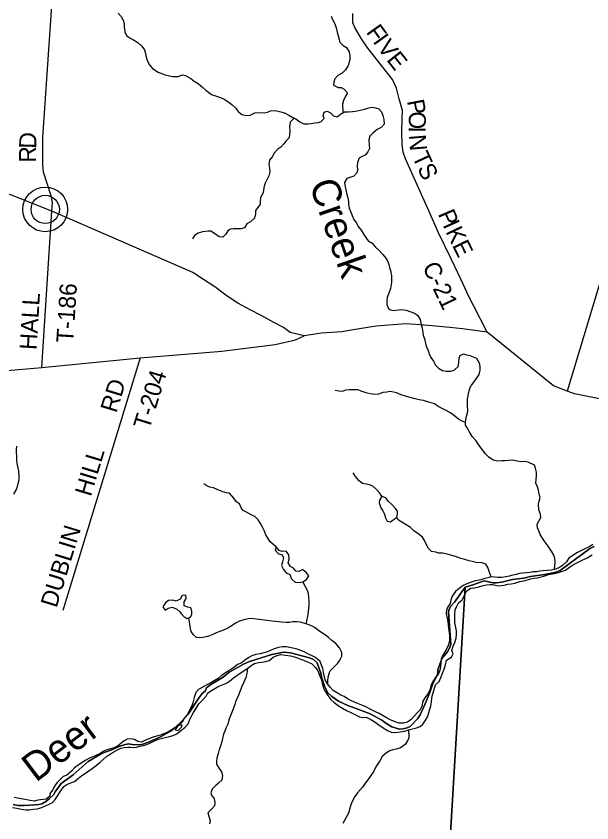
# Model space of a CAD drawing. Extents: x 1643459 to 2064572, y 425441 to 780708.
# Drawn here: x 1774988 to 1785105, y 584838 to 599024 of the extents above; entities that cross this region are included whole.
import ezdxf

# ---------------------------------------------------------------- set-up
doc = ezdxf.new("R2010")
doc.units = 0
for name, color, linetype in [('GE_P_Alignment_100_Curve_Data', 7, 'Continuous'), ('GM_X_City_Street', 7, 'Continuous'), ('GM_X_Interchange_Ramps', 7, 'Continuous'), ('GM_X_Major_River', 7, 'Continuous'), ('GM_X_Major_River_Text', 7, 'Continuous'), ('GM_X_Minor_Lake', 7, 'Continuous'), ('GM_X_Rail_Line', 7, 'Continuous'), ('GM_X_Section_Text', 7, 'Continuous'), ('GM_X_State_Shield', 7, 'Continuous'), ('GM_X_Township_Subdivision_Text', 7, 'Continuous'), ('GM_X_Unincorporated_Text', 7, 'Continuous'), ('GM_X_US_Route', 7, 'Continuous')]:
    doc.layers.add(name, color=color, linetype=linetype)

msp = doc.modelspace()

# ---------------------------------------------------------------- linework, layer by layer
at = {"layer": 'GE_P_Alignment_100_Curve_Data'}
for radius in [393, 249]:
    msp.add_circle((1775499, 595625), radius, dxfattribs=at)
at = {"layer": 'GM_X_City_Street'}
for points in [[(1785145, 589695), (1785063, 589654), (1784546, 589274), (1784474, 589244), (1784280, 589203), (1784028, 589172), (1783911, 589141), (1783711, 589116), (1783521, 589072), (1783425, 589061), (1783363, 589061), (1783215, 589096), (1783016, 589021), (1782878, 588982), (1782690, 588716), (1782624, 588650), (1782596, 588598), (1782584, 588542), (1782625, 587974), (1782600, 587898), (1782566, 587844), (1782481, 587740), (1782459, 587690), (1782396, 587526), (1782400, 587454), (1782358, 587382), (1782305, 587268), (1782264, 587148), (1782175, 586930), (1782088, 586740), (1782042, 586666), (1781913, 586530), (1781861, 586506), (1781789, 586490), (1781723, 586483), (1781591, 586526), (1781483, 586588), (1781413, 586645), (1781210, 586756), (1780900, 586874), (1780826, 586895), (1780651, 586980), (1780533, 587057), (1780465, 587127), (1780408, 587240), (1780362, 587381), (1780351, 587455), (1780276, 587652), (1780212, 587710), (1780142, 587741), (1779812, 587829), (1779684, 587838), (1779484, 587801), (1779089, 587676), (1778973, 587621), (1778728, 587480), (1778625, 587398), (1778391, 587261), (1778334, 587211), (1778310, 587155), (1778256, 587111), (1778205, 587043), (1778008, 586748), (1777895, 586620), (1777774, 586506), (1777710, 586458), (1777525, 586351), (1777283, 586244), (1777197, 586217), (1777056, 586207), (1776960, 586226), (1776886, 586210), (1776808, 586187), (1776668, 586121), (1776537, 586074), (1776421, 586016), (1776252, 585915), (1775989, 585682), (1775776, 585530), (1775671, 585384), (1775645, 585332), (1775573, 585265), (1775508, 585213), (1775442, 585175), (1775388, 585159), (1775318, 585152), (1775134, 585141), (1775022, 585143), (1774936, 585160)], [(1785638, 551176), (1783571, 551280), (1780637, 551427), (1780907, 555957), (1781210, 561021), (1781241, 561540), (1781479, 565536), (1782039, 574916), (1782573, 583864), (1782878, 588982), (1783016, 589021), (1783215, 589096), (1783363, 589061), (1783425, 589061), (1783521, 589072), (1783711, 589116), (1783911, 589141), (1784028, 589172), (1784280, 589203), (1784474, 589244), (1784546, 589274), (1785063, 589654), (1785145, 589695)], [(1774936, 585160), (1775022, 585143), (1775134, 585141), (1775318, 585152), (1775388, 585159), (1775442, 585175), (1775508, 585213), (1775573, 585265), (1775645, 585332), (1775671, 585384), (1775776, 585530), (1775989, 585682), (1776252, 585915), (1776421, 586016), (1776537, 586074), (1776668, 586121), (1776808, 586187), (1776886, 586210), (1776960, 586226), (1777056, 586207), (1777197, 586217), (1777283, 586244), (1777525, 586351), (1777710, 586458), (1777774, 586506), (1777895, 586620), (1778008, 586748), (1778205, 587043), (1778256, 587111), (1778310, 587155), (1778334, 587211), (1778391, 587261), (1778625, 587398), (1778728, 587480), (1778973, 587621), (1779089, 587676), (1779484, 587801), (1779684, 587838), (1779812, 587829), (1780142, 587741), (1780212, 587710), (1780276, 587652), (1780351, 587455), (1780362, 587381), (1780408, 587240), (1780465, 587127), (1780533, 587057), (1780651, 586980), (1780826, 586895), (1780900, 586874), (1781210, 586756), (1781413, 586645), (1781483, 586588), (1781591, 586526), (1781723, 586483), (1781789, 586490), (1781861, 586506), (1781913, 586530), (1782042, 586666), (1782088, 586740), (1782175, 586930), (1782264, 587148), (1782305, 587268), (1782358, 587382), (1782400, 587454), (1782396, 587526), (1782459, 587690), (1782481, 587740), (1782566, 587844), (1782600, 587898), (1782625, 587974), (1782584, 588542), (1782596, 588598), (1782624, 588650), (1782690, 588716), (1782878, 588982), (1782573, 583864)]]:
    msp.add_lwpolyline(points, dxfattribs=at)
at = {"layer": 'GM_X_Major_River_Text'}
for points in [[(1785328, 606791), (1786619, 602390), (1786660, 602213), (1786853, 601568), (1786925, 601173), (1786882, 600934), (1786380, 597820), (1786372, 597734), (1786255, 597600), (1785662, 596965), (1785638, 596798), (1785873, 595554), (1785859, 595459), (1785408, 594758), (1785283, 594487), (1785225, 594273), (1784673, 592431)], [(1775613, 595594), (1775628, 595745), (1775605, 595867), (1775470, 596279), (1775455, 596409), (1775456, 596891), (1775858, 602814), (1775878, 602941), (1775893, 603105), (1775919, 603416), (1775936, 603556), (1775980, 603638), (1776241, 603970), (1776327, 604068), (1776452, 604256), (1776531, 604386), (1776729, 604627), (1776882, 604731), (1777131, 604864), (1777265, 604900), (1779128, 605436)], [(1775439, 592847), (1775613, 595594)], [(1777170, 593015), (1775811, 588571)]]:
    msp.add_lwpolyline(points, dxfattribs=at)
at = {"layer": 'GM_X_Minor_Lake'}
for points in [[(1783266, 593466), (1783028, 593933), (1782946, 594092), (1782804, 594401), (1782627, 594767), (1782411, 595212), (1782241, 595598), (1781831, 596516), (1781792, 596631), (1781772, 596765), (1781768, 596986), (1781773, 597227), (1781776, 597363), (1781721, 597572), (1781670, 597759), (1781602, 597908), (1781344, 598240), (1781166, 598461), (1781057, 598626), (1780944, 598813), (1780902, 598906), (1780905, 599068)], [(1783266, 593466), (1782829, 593523), (1782607, 593550), (1782301, 593577), (1782006, 593599), (1781838, 593612), (1781317, 593572), (1780912, 593508), (1780713, 593475), (1780354, 593449), (1780048, 593400), (1779803, 593461), (1779688, 593546), (1779514, 593637), (1779304, 593753), (1779102, 593858), (1778885, 593979), (1778699, 594101), (1778479, 594264), (1778282, 594394), (1778090, 594513), (1775613, 595594), (1772804, 596711)], [(1792934, 588598), (1792450, 588716), (1791683, 588942), (1788162, 590231), (1787955, 590362), (1786367, 591862), (1785471, 592247), (1784800, 592384), (1784673, 592431), (1784433, 592524), (1783266, 593466)], [(1773680, 592693), (1775439, 592847), (1777170, 593015), (1778600, 593134), (1779540, 593250), (1779895, 593329), (1780048, 593400)]]:
    msp.add_lwpolyline(points, dxfattribs=at)
at = {"layer": 'GM_X_Rail_Line'}
msp.add_line((1775499, 595625), (1775499, 595625), dxfattribs=at)
at = {"layer": 'GM_X_Township_Subdivision_Text'}
msp.add_line((1780086, 589242), (1780052, 589271), dxfattribs=at)
for points in [[(1781602, 590422), (1781528, 590492), (1781488, 590549), (1781416, 590581), (1781374, 590513), (1781366, 590463), (1781395, 590377), (1781429, 590326), (1781461, 590268), (1781481, 590200), (1781510, 590142), (1781566, 590131), (1781677, 590215)], [(1781677, 590215), (1781689, 590265), (1781691, 590317), (1781650, 590373), (1781602, 590422)], [(1779557, 589691), (1779539, 589631), (1779600, 589570), (1779660, 589550), (1779688, 589498), (1779666, 589429), (1779651, 589361), (1779685, 589291), (1779735, 589235), (1779797, 589204), (1779828, 589130), (1779890, 589073), (1779966, 589065), (1780026, 589076), (1780088, 589120), (1780129, 589180), (1780086, 589242)], [(1780052, 589271), (1780025, 589291), (1779955, 589259), (1779905, 589264), (1779861, 589318), (1779809, 589346), (1779770, 589409), (1779784, 589475), (1779782, 589553), (1779735, 589614), (1779663, 589610), (1779611, 589630), (1779557, 589691)], [(1777862, 588546), (1777890, 588518), (1777932, 588468), (1777990, 588432), (1778050, 588455), (1778074, 588507), (1778076, 588562), (1778059, 588620), (1778007, 588630), (1777941, 588655), (1777941, 588723), (1777975, 588783), (1777968, 588839), (1777906, 588835), (1777871, 588773), (1777801, 588734), (1777739, 588754), (1777665, 588746), (1777611, 588709), (1777568, 588639), (1777606, 588576)], [(1777606, 588576), (1777662, 588614), (1777728, 588628), (1777812, 588595), (1777862, 588546)]]:
    msp.add_lwpolyline(points, dxfattribs=at)
at = {"layer": 'GM_X_Unincorporated_Text'}
for points in [[(1785125, 589731), (1785062, 589689), (1784992, 589663), (1784926, 589630), (1784852, 589592), (1784789, 589550), (1784697, 589486), (1784657, 589427), (1784592, 589363), (1784536, 589331), (1784472, 589299), (1784394, 589282), (1784320, 589276), (1784248, 589272), (1784192, 589261), (1784130, 589251), (1784074, 589251), (1784013, 589241), (1783959, 589234), (1783889, 589226), (1783833, 589220), (1783777, 589207), (1783719, 589195), (1783653, 589177), (1783595, 589164), (1783515, 589152), (1783453, 589154), (1783403, 589157), (1783337, 589163), (1783277, 589145), (1783222, 589135), (1783152, 589110), (1783038, 589088), (1782966, 589065), (1782898, 589033), (1782846, 589011), (1782771, 588959), (1782709, 588906), (1782649, 588826), (1782626, 588754), (1782614, 588693), (1782572, 588634), (1782549, 588577), (1782545, 588517), (1782561, 588435), (1782572, 588381), (1782582, 588315), (1782586, 588262), (1782599, 588180), (1782603, 588130), (1782601, 588064), (1782598, 588008), (1782582, 587958), (1782556, 587904), (1782522, 587848), (1782479, 587776), (1782459, 587718), (1782453, 587653), (1782448, 587581), (1782432, 587521), (1782408, 587457), (1782353, 587387), (1782303, 587311), (1782276, 587245), (1782260, 587171), (1782222, 587109), (1782169, 587037), (1782127, 586965)], [(1782236, 586754), (1782254, 586818), (1782273, 586890), (1782285, 586962), (1782293, 587030), (1782304, 587089), (1782326, 587165), (1782359, 587263), (1782421, 587325), (1782457, 587407), (1782482, 587469), (1782512, 587539), (1782532, 587615), (1782553, 587697), (1782639, 587753), (1782666, 587809), (1782642, 587871), (1782666, 587943), (1782695, 588011), (1782723, 588085), (1782725, 588151), (1782726, 588214), (1782710, 588304), (1782700, 588358), (1782695, 588428), (1782697, 588490), (1782705, 588581), (1782730, 588647), (1782764, 588707), (1782824, 588761), (1782865, 588843), (1782905, 588911), (1782971, 588962), (1783042, 588972), (1783120, 588990), (1783196, 589011), (1783252, 589023), (1783316, 589029), (1783366, 589032), (1783458, 589008), (1783510, 589010), (1783562, 589019), (1783628, 589035), (1783690, 589043), (1783752, 589052), (1783837, 589080), (1783907, 589096), (1784035, 589127), (1784085, 589139), (1784143, 589149), (1784263, 589178), (1784341, 589206), (1784446, 589225), (1784504, 589233), (1784574, 589256), (1784642, 589282), (1784710, 589334), (1784763, 589368), (1784843, 589411), (1784897, 589441), (1785023, 589497), (1785110, 589552)], [(1782127, 586965), (1782123, 586903), (1782088, 586827), (1782038, 586771), (1781986, 586717), (1781927, 586653), (1781867, 586610), (1781797, 586588), (1781721, 586590), (1781667, 586607), (1781561, 586651), (1781507, 586676), (1781437, 586722), (1781370, 586763), (1781304, 586793), (1781220, 586834), (1781132, 586880), (1781060, 586909), (1780974, 586941), (1780882, 586982), (1780810, 587018), (1780751, 587059), (1780693, 587083), (1780615, 587128), (1780559, 587168), (1780509, 587223), (1780458, 587285), (1780418, 587350), (1780404, 587406), (1780392, 587484), (1780377, 587550), (1780353, 587611), (1780333, 587673), (1780246, 587744), (1780190, 587774), (1780124, 587806), (1780036, 587849), (1779964, 587883), (1779906, 587900), (1779818, 587918), (1779736, 587933), (1779664, 587933), (1779600, 587922), (1779520, 587898), (1779468, 587874), (1779390, 587842), (1779340, 587825), (1779277, 587813), (1779199, 587799), (1779127, 587772), (1779077, 587746), (1778999, 587690), (1778940, 587648), (1778880, 587623), (1778806, 587565), (1778695, 587495), (1778597, 587432), (1778539, 587378), (1778467, 587336), (1778412, 587300), (1778352, 587272), (1778288, 587235), (1778190, 587183), (1778143, 587129), (1778119, 587045), (1778092, 586951), (1778076, 586895), (1778040, 586833), (1778001, 586745), (1777949, 586685), (1777903, 586609), (1777846, 586555), (1777780, 586515), (1777710, 586470), (1777656, 586432), (1777595, 586408), (1777523, 586380), (1777453, 586363), (1777395, 586343), (1777317, 586317), (1777259, 586292), (1777188, 586254), (1777124, 586268), (1777070, 586301), (1776996, 586313), (1776936, 586307), (1776886, 586280), (1776766, 586184), (1776706, 586158), (1776631, 586131), (1776581, 586119), (1776517, 586095), (1776463, 586059), (1776387, 586020), (1776330, 585998), (1776274, 585974), (1776198, 585932), (1776142, 585896), (1776078, 585855), (1776015, 585803), (1775963, 585747)], [(1776086, 585624), (1776145, 585670), (1776207, 585714), (1776267, 585753), (1776325, 585795), (1776396, 585849), (1776458, 585897), (1776516, 585953), (1776575, 586002), (1776629, 586038), (1776707, 586088), (1776769, 586124), (1776826, 586152), (1776884, 586165), (1776948, 586169), (1777000, 586169), (1777052, 586164), (1777104, 586170), (1777162, 586184), (1777224, 586198), (1777284, 586217), (1777336, 586237), (1777419, 586281), (1777491, 586308), (1777559, 586326), (1777609, 586336), (1777685, 586355), (1777749, 586375), (1777813, 586405), (1777878, 586457), (1777952, 586512), (1778010, 586582), (1778037, 586642), (1778075, 586724), (1778106, 586776), (1778146, 586842), (1778200, 586928), (1778261, 586998), (1778327, 587066), (1778355, 587122), (1778418, 587168), (1778508, 587217), (1778566, 587249), (1778628, 587273), (1778686, 587293), (1778739, 587329), (1778807, 587390), (1778867, 587432), (1779066, 587563), (1779120, 587605), (1779179, 587641), (1779249, 587655), (1779307, 587662), (1779377, 587676), (1779433, 587690), (1779503, 587754), (1779577, 587783), (1779636, 587797), (1779722, 587788), (1779810, 587772), (1779896, 587753), (1779975, 587725), (1780067, 587686), (1780121, 587664), (1780179, 587638), (1780251, 587567), (1780289, 587513), (1780320, 587436), (1780348, 587364), (1780373, 587270), (1780391, 587213), (1780413, 587157), (1780463, 587076), (1780516, 587008), (1780576, 586954), (1780644, 586903), (1780724, 586854), (1780793, 586816), (1780845, 586792), (1780905, 586759), (1780963, 586729), (1781023, 586700), (1781079, 586690), (1781141, 586694), (1781221, 586657), (1781281, 586619), (1781359, 586560), (1781440, 586506), (1781512, 586461), (1781576, 586431), (1781660, 586424), (1781738, 586436), (1781820, 586451), (1781882, 586471), (1781951, 586489), (1782003, 586501), (1782087, 586534), (1782137, 586576), (1782175, 586634), (1782216, 586700), (1782236, 586754)], [(1777903, 586560), (1777831, 586542), (1777782, 586476), (1777834, 586462), (1777867, 586494)], [(1777867, 586494), (1777896, 586523), (1777903, 586560)], [(1774925, 585107), (1775001, 585096), (1775083, 585078), (1775161, 585065), (1775217, 585067), (1775285, 585081), (1775355, 585086), (1775437, 585106), (1775514, 585142), (1775568, 585164), (1775626, 585197), (1775672, 585251), (1775711, 585303), (1775747, 585363), (1775783, 585419), (1775824, 585475), (1775878, 585513), (1775932, 585533), (1776012, 585566), (1776086, 585624)], [(1775963, 585747), (1775877, 585679), (1775812, 585654), (1775762, 585602), (1775708, 585548), (1775663, 585484), (1775631, 585420), (1775577, 585356), (1775577, 585306), (1775514, 585252), (1775418, 585241), (1775368, 585239), (1775308, 585221), (1775232, 585230), (1775178, 585240), (1775112, 585252), (1775016, 585273), (1774952, 585281)]]:
    msp.add_lwpolyline(points, dxfattribs=at)
at = {"layer": 'GM_X_US_Route'}
for points in [[(1776781, 599075), (1776833, 599015), (1776869, 598954), (1776884, 598896), (1776886, 598834), (1776899, 598747), (1776927, 598685), (1776991, 598639), (1777051, 598606), (1777129, 598560), (1777196, 598495), (1777242, 598430), (1777259, 598366), (1777275, 598304), (1777289, 598249), (1777324, 598175), (1777386, 598106), (1777482, 598038), (1777606, 597989), (1777658, 597978), (1777734, 597962), (1777834, 597965), (1777912, 597991), (1777963, 597983), (1778056, 597926), (1778118, 597882), (1778184, 597841), (1778266, 597768), (1778322, 597722), (1778419, 597647), (1778491, 597623), (1778581, 597594), (1778641, 597562), (1778705, 597525), (1778781, 597468), (1778849, 597406), (1778892, 597345), (1778952, 597293), (1779032, 597274), (1779101, 597284), (1779183, 597324), (1779279, 597331), (1779353, 597325), (1779404, 597335), (1779460, 597356), (1779544, 597362), (1779660, 597337), (1779716, 597315), (1779778, 597284), (1779848, 597240), (1779900, 597217), (1779972, 597167), (1780044, 597130), (1780120, 597128), (1780172, 597136), (1780236, 597147), (1780299, 597153), (1780351, 597171), (1780399, 597225), (1780382, 597279), (1780402, 597337), (1780454, 597355), (1780510, 597326), (1780564, 597270), (1780632, 597256), (1780685, 597299), (1780761, 597343), (1780827, 597339), (1780896, 597348), (1780948, 597354), (1781012, 597366), (1781062, 597374), (1781118, 597387), (1781183, 597411), (1781239, 597421), (1781309, 597414), (1781361, 597394), (1781409, 597344), (1781432, 597279), (1781450, 597205), (1781453, 597127), (1781403, 597063), (1781334, 597029), (1781254, 596969), (1781203, 596913), (1781187, 596847), (1781194, 596757), (1781196, 596698), (1781167, 596640), (1781121, 596582), (1781068, 596555), (1781018, 596529)], [(1780524, 599025), (1780546, 598966), (1780590, 598890), (1780613, 598820), (1780627, 598745), (1780644, 598679), (1780666, 598614), (1780674, 598564), (1780735, 598508), (1780793, 598471), (1780841, 598399), (1780850, 598322), (1780850, 598270), (1780841, 598212), (1780823, 598154), (1780778, 598080), (1780718, 598024), (1780643, 597980), (1780591, 597924), (1780568, 597860), (1780566, 597808), (1780648, 597767), (1780700, 597767), (1780754, 597741), (1780808, 597676), (1780773, 597616), (1780738, 597540)], [(1780738, 597540), (1780724, 597474), (1780729, 597332)], [(1779872, 597230), (1779803, 597160), (1779793, 597077), (1779800, 597019), (1779794, 596933), (1779779, 596881), (1779725, 596827), (1779692, 596777), (1779642, 596719), (1779584, 596683), (1779519, 596611), (1779494, 596557), (1779440, 596493), (1779427, 596423), (1779441, 596353), (1779448, 596288), (1779430, 596214), (1779401, 596156), (1779363, 596084), (1779344, 596034), (1779336, 595968), (1779327, 595914), (1779283, 595832), (1779278, 595767), (1779276, 595717), (1779235, 595659), (1779197, 595605), (1779196, 595545), (1779176, 595469), (1779107, 595407), (1779043, 595371), (1779000, 595303), (1778938, 595283), (1778884, 595286), (1778810, 595284), (1778757, 595280), (1778707, 595250), (1778673, 595188), (1778622, 595136), (1778554, 595145), (1778492, 595189), (1778412, 595240), (1778360, 595244), (1778262, 595229), (1778187, 595205), (1778123, 595165), (1778085, 595109)], [(1781018, 596529), (1780989, 596451), (1780983, 596386), (1780985, 596324), (1780974, 596268), (1780920, 596210), (1780867, 596190), (1780797, 596171), (1780758, 596099), (1780762, 596048), (1780776, 595996), (1780791, 595912), (1780817, 595831), (1780826, 595765), (1780830, 595709), (1780839, 595650), (1780867, 595578), (1780891, 595516), (1780924, 595449), (1780968, 595385), (1780999, 595324), (1781049, 595262), (1781105, 595175), (1781176, 595074), (1781244, 595030), (1781302, 594963), (1781363, 594907), (1781431, 594834), (1781485, 594768), (1781518, 594709), (1781536, 594659), (1781550, 594601), (1781569, 594550), (1781583, 594458), (1781584, 594400), (1781582, 594341), (1781569, 594233), (1781537, 594155), (1781508, 594075), (1781502, 594025), (1781501, 593952), (1781537, 593872), (1781605, 593845), (1781707, 593857), (1781765, 593863), (1781843, 593854), (1781987, 593799), (1782041, 593763), (1782087, 593688), (1782100, 593626), (1782124, 593535), (1782141, 593415), (1782166, 593350), (1782196, 593222), (1782231, 593147), (1782247, 593083), (1782276, 593021), (1782322, 592956), (1782358, 592888), (1782413, 592833), (1782479, 592795), (1782549, 592780), (1782620, 592780), (1782688, 592796), (1782754, 592861), (1782767, 592930), (1782774, 593008), (1782790, 593058), (1782850, 593084), (1782902, 593069), (1782958, 593057), (1783018, 593033), (1783078, 593012), (1783126, 592926), (1783137, 592861), (1783139, 592797), (1783116, 592723), (1783086, 592669), (1782981, 592524)], [(1782883, 591877), (1782828, 591903), (1782762, 591936), (1782668, 592015), (1782611, 592053), (1782535, 592096), (1782477, 592124), (1782405, 592162), (1782337, 592207), (1782263, 592229), (1782201, 592248), (1782145, 592264), (1782071, 592277), (1781979, 592301), (1781889, 592326), (1781831, 592340), (1781756, 592366), (1781672, 592399), (1781618, 592413), (1781560, 592424), (1781500, 592412), (1781430, 592404), (1781357, 592379), (1781273, 592369), (1781207, 592381), (1781155, 592394), (1781053, 592430), (1781000, 592453), (1780927, 592455), (1780843, 592454), (1780777, 592448), (1780717, 592426), (1780661, 592429), (1780595, 592439)], [(1784450, 589297), (1784461, 589420), (1784453, 589486), (1784435, 589546), (1784396, 589616), (1784340, 589701), (1784266, 589800), (1784199, 589908), (1784175, 589971), (1784147, 590023), (1784146, 590089), (1784180, 590155), (1784208, 590207), (1784203, 590267), (1784171, 590344), (1784169, 590440), (1784182, 590492), (1784196, 590560), (1784180, 590616), (1784167, 590691), (1784147, 590745), (1784123, 590813), (1784124, 590884), (1784132, 590936), (1784130, 591004), (1784115, 591076), (1784095, 591126), (1783987, 591183), (1783929, 591195), (1783877, 591188), (1783785, 591200), (1783711, 591213), (1783651, 591209), (1783573, 591203), (1783523, 591204), (1783451, 591198), (1783373, 591217), (1783293, 591271), (1783235, 591326), (1783110, 591495), (1783074, 591555), (1783009, 591628), (1782967, 591692), (1782911, 591783), (1782882, 591833), (1782882, 591891), (1782900, 591987), (1782917, 592041), (1782925, 592093), (1782921, 592164), (1782918, 592232), (1782918, 592296), (1782936, 592384), (1782957, 592460), (1782981, 592524)], [(1774948, 590616), (1774991, 590688), (1775009, 590750), (1775025, 590804), (1775042, 590869), (1775042, 590939), (1775034, 591027), (1775017, 591105), (1775005, 591156), (1774999, 591218), (1774998, 591288), (1774996, 591356), (1774994, 591408), (1774999, 591464)], [(1781416, 590581), (1781373, 590644), (1781315, 590706), (1781255, 590759), (1781195, 590781), (1781137, 590795), (1781073, 590808), (1781014, 590852), (1780952, 590927), (1780912, 590991)], [(1779557, 589691), (1779453, 589782), (1779374, 589902), (1779348, 589981), (1779316, 590037), (1779283, 590101), (1779239, 590164), (1779185, 590224), (1779127, 590251), (1779036, 590301), (1778980, 590328), (1778942, 590378), (1778914, 590446), (1778862, 590483), (1778813, 590547), (1778737, 590638), (1778687, 590642), (1778619, 590659), (1778521, 590701), (1778457, 590728), (1778393, 590740), (1778339, 590762), (1778288, 590801)], [(1783337, 589163), (1783299, 589257), (1783275, 589330), (1783244, 589388), (1783172, 589410), (1783072, 589419), (1783004, 589435), (1782950, 589448), (1782870, 589468), (1782800, 589487), (1782706, 589519), (1782646, 589538), (1782562, 589560), (1782478, 589581), (1782418, 589583), (1782362, 589595), (1782288, 589608), (1782234, 589662), (1782203, 589715), (1782167, 589801), (1782127, 589863), (1782046, 589928), (1781984, 589966), (1781916, 590029), (1781844, 590078), (1781764, 590128), (1781705, 590161), (1781683, 590202)], [(1780089, 588338), (1780099, 588398), (1780111, 588468), (1780126, 588552), (1780138, 588661), (1780139, 588741), (1780131, 588803), (1780123, 588869), (1780109, 588926), (1780026, 589076)], [(1780463, 587282), (1780468, 587333), (1780470, 587397), (1780488, 587463), (1780509, 587513), (1780563, 587571), (1780633, 587641), (1780678, 587697), (1780710, 587771), (1780710, 587831), (1780671, 587918), (1780605, 587990), (1780537, 588047), (1780478, 588095), (1780422, 588138), (1780324, 588204), (1780226, 588279), (1780136, 588322), (1780063, 588346), (1779977, 588369), (1779923, 588371), (1779853, 588371), (1779800, 588364), (1779732, 588364), (1779652, 588369), (1779600, 588375), (1779548, 588379), (1779484, 588383), (1779404, 588398), (1779348, 588404), (1779298, 588407), (1779206, 588417), (1779120, 588430), (1779068, 588426), (1778992, 588410), (1778914, 588383), (1778842, 588349), (1778782, 588311), (1778705, 588259), (1778629, 588228), (1778569, 588204), (1778501, 588182), (1778445, 588152), (1778384, 588127), (1778328, 588107), (1778266, 588095), (1778210, 588094), (1778160, 588098), (1778102, 588144), (1778061, 588203), (1778051, 588257), (1778022, 588444)], [(1779056, 587557), (1779040, 587465), (1779025, 587393), (1778991, 587311), (1778956, 587237), (1778922, 587161), (1778894, 587085), (1778867, 587021), (1778845, 586967), (1778833, 586917), (1778806, 586855), (1778770, 586767), (1778723, 586649), (1778705, 586573), (1778671, 586501), (1778656, 586450), (1778634, 586398), (1778614, 586320), (1778601, 586264), (1778565, 586160), (1778552, 586106), (1778536, 586056), (1778516, 585978), (1778510, 585926), (1778511, 585868), (1778557, 585795), (1778595, 585733), (1778612, 585668), (1778602, 585590), (1778546, 585536), (1778495, 585495), (1778433, 585433), (1778409, 585365), (1778428, 585314), (1778466, 585264), (1778480, 585190), (1778472, 585138), (1778415, 585074), (1778357, 585014), (1778373, 584954), (1778398, 584873), (1778384, 584821)], [(1781882, 586471), (1781890, 586335), (1781863, 586283), (1781825, 586213), (1781743, 586157), (1781669, 586133), (1781610, 586120), (1781556, 586102), (1781496, 586070), (1781420, 586004), (1781377, 585930), (1781309, 585824), (1781272, 585746), (1781184, 585616), (1781109, 585521), (1781073, 585467), (1780988, 585363), (1780942, 585299), (1780906, 585235), (1780877, 585175), (1780855, 585113), (1780830, 585011), (1780726, 584825)], [(1781888, 586415), (1781890, 586335), (1781863, 586283), (1781825, 586213), (1781743, 586157), (1781669, 586133), (1781610, 586120), (1781556, 586102), (1781496, 586070), (1781420, 586004), (1781377, 585930), (1781309, 585824), (1781272, 585746), (1781184, 585616), (1781109, 585521), (1781073, 585467), (1780988, 585363), (1780942, 585299), (1780906, 585235), (1780877, 585175), (1780855, 585113), (1780830, 585011), (1780726, 584825)]]:
    msp.add_lwpolyline(points, dxfattribs=at)

# ---------------------------------------------------------------- texts
at = {"layer": 'GM_X_Interchange_Ramps'}
msp.add_text('Creek', height=500, rotation=289.1152, dxfattribs=at).set_placement((1780134, 596070))
at = {"layer": 'GM_X_Major_River'}
for s, rotation, p in [('D', 88.5208, (1775339, 596691)), ('R', 89.9766, (1775339, 596447)), ('T-186', 86.3357, (1775991, 593272)), ('HALL', 86.6334, (1775348, 593149)), ('T-204', 72.8979, (1777328, 591740)), ('RD', 72.9697, (1776749, 592033)), ('HILL', 73.1085, (1776300, 590563)), ('DUBLIN', 72.8834, (1775697, 588606))]:
    msp.add_text(s, height=300, rotation=rotation, dxfattribs=at).set_placement(p)
at = {"layer": 'GM_X_Section_Text'}
for s, rotation, p in [('F', 305.6487, (1781129, 598742)), ('I', 305.7354, (1781247, 598577)), ('V', 306.6488, (1781322, 598473)), ('E', 308.3058, (1781485, 598254)), ('P', 280.5794, (1781854, 597533)), ('O', 269.5592, (1781890, 597349)), ('I', 269.3052, (1781888, 597086)), ('N', 274.6397, (1781888, 596932)), ('T', 295.0199, (1781939, 596557)), ('S', 294.5014, (1782033, 596354)), ('P', 293.178, (1782395, 595547)), ('I', 294.2853, (1782478, 595355)), ('K', 295.4037, (1782531, 595237)), ('E', 295.932, (1782645, 594996)), ('C-21', 295.5233, (1782121, 594618))]:
    msp.add_text(s, height=300, rotation=rotation, dxfattribs=at).set_placement(p)
at = {"layer": 'GM_X_State_Shield'}
msp.add_text('Deer', height=500, rotation=37.1115, dxfattribs=at).set_placement((1775333, 585540))

doc.saveas('drawing.dxf')
